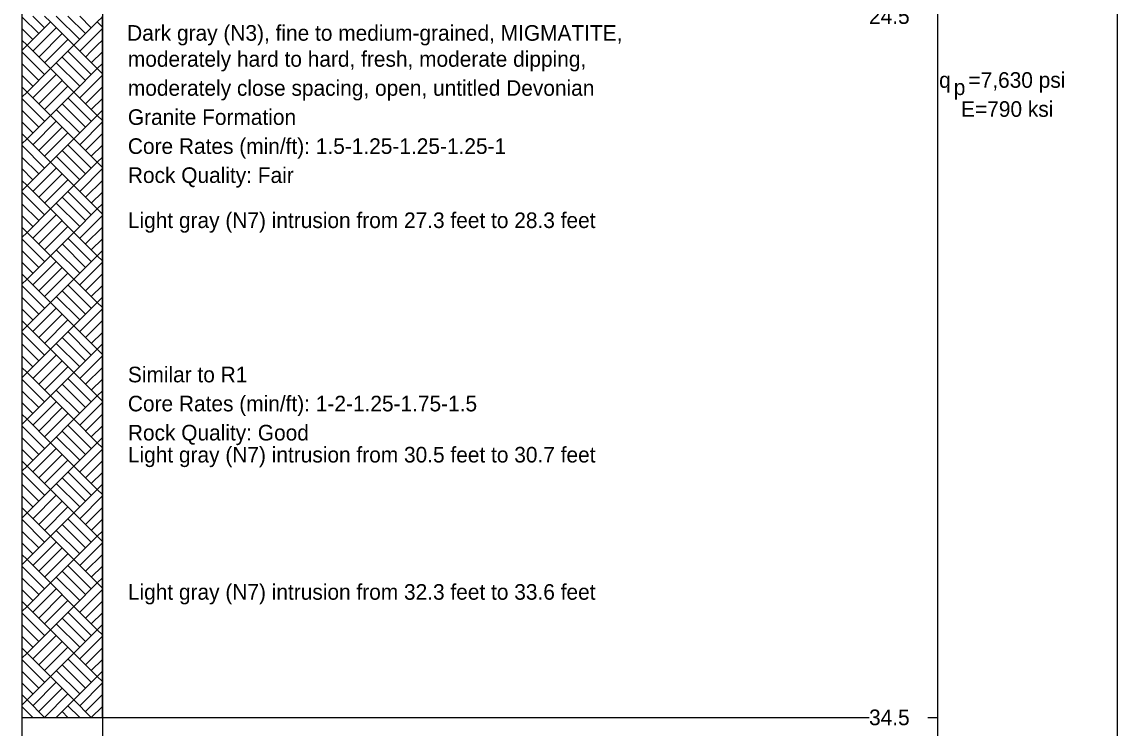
# Model space of a CAD drawing. Extents: x 9419 to 9552, y 6780 to 6865.
# Drawn here: x 9438.31 to 9453.95, y 6812.36 to 6822.43 of the extents above; entities that cross this region are included whole.
import ezdxf

# ---------------------------------------------------------------- set-up
doc = ezdxf.new("R2010")
doc.units = 0
doc.layers.add('7', color=7, linetype='Continuous')
doc.layers.add('8', color=7, linetype='Continuous')

msp = doc.modelspace()

# ---------------------------------------------------------------- linework, layer by layer
at = {"layer": '7'}
for p, q in [((9438.314, 6822.511), (9438.314, 6822.011)), ((9439.463, 6822.011), (9439.463, 6822.511)), ((9438.314, 6822.011), (9438.314, 6812.511)), ((9439.463, 6812.511), (9439.463, 6822.011)), ((9438.314, 6812.511), (9439.463, 6812.511))]:
    msp.add_line(p, q, dxfattribs=at)
for points in [[(9453.945, 6860.114), (9453.945, 6821.983)], [(9438.314, 6850.528), (9438.314, 6821.983)], [(9439.463, 6850.528), (9439.463, 6821.983)], [(9451.38, 6850.528), (9451.38, 6821.983)], [(9438.314, 6822.038), (9438.314, 6796.983)], [(9439.463, 6822.038), (9439.463, 6796.983)], [(9451.38, 6822.038), (9451.38, 6796.983)], [(9453.945, 6822.038), (9453.945, 6791.992)], [(9439.463, 6812.511), (9450.405, 6812.511)], [(9451.244, 6812.511), (9451.38, 6812.511)]]:
    msp.add_lwpolyline(points, dxfattribs=at)
at = {"layer": '8'}
for p, q in [((9438.314, 6822.501), (9438.555, 6822.261)), ((9438.722, 6822.427), (9438.389, 6822.094)), ((9438.722, 6822.427), (9438.389, 6822.094)), ((9438.472, 6822.511), (9438.639, 6822.344)), ((9438.639, 6822.511), (9438.722, 6822.427)), ((9439.055, 6822.094), (9438.722, 6822.427)), ((9438.722, 6822.427), (9439.055, 6822.094)), ((9438.805, 6822.511), (9439.139, 6822.177)), ((9438.972, 6822.511), (9439.222, 6822.261)), ((9439.389, 6822.427), (9439.055, 6822.094)), ((9439.139, 6822.511), (9439.305, 6822.344)), ((9439.463, 6822.501), (9439.389, 6822.427)), ((9439.389, 6822.427), (9439.463, 6822.353)), ((9438.314, 6822.335), (9438.472, 6822.177)), ((9438.805, 6822.344), (9438.472, 6822.011)), ((9438.889, 6822.261), (9438.555, 6821.927)), ((9439.463, 6822.335), (9439.139, 6822.011)), ((9438.314, 6822.168), (9438.389, 6822.094)), ((9438.389, 6822.094), (9438.314, 6822.02)), ((9438.389, 6822.094), (9438.722, 6821.761)), ((9438.972, 6822.177), (9438.639, 6821.844)), ((9439.055, 6822.094), (9438.722, 6821.761)), ((9439.055, 6822.094), (9439.389, 6821.761)), ((9439.389, 6822.094), (9439.305, 6822.011)), ((9439.389, 6822.094), (9439.305, 6822.011)), ((9439.463, 6822.168), (9439.389, 6822.094)), ((9439.463, 6822.168), (9439.389, 6822.094)), ((9438.314, 6822.001), (9438.639, 6821.677)), ((9438.472, 6822.011), (9438.472, 6822.011)), ((9438.889, 6821.927), (9439.222, 6821.594)), ((9438.972, 6822.011), (9439.305, 6821.677)), ((9439.139, 6822.011), (9439.139, 6822.011)), ((9439.305, 6822.011), (9439.222, 6821.927)), ((9439.463, 6822.001), (9439.305, 6821.844)), ((9438.314, 6821.835), (9438.555, 6821.594)), ((9438.722, 6821.761), (9438.389, 6821.427)), ((9438.722, 6821.761), (9438.389, 6821.427)), ((9439.055, 6821.427), (9438.722, 6821.761)), ((9438.722, 6821.761), (9439.055, 6821.427)), ((9438.805, 6821.844), (9439.139, 6821.511)), ((9439.389, 6821.761), (9439.055, 6821.427)), ((9439.389, 6821.761), (9439.055, 6821.427)), ((9439.463, 6821.835), (9439.389, 6821.761)), ((9439.463, 6821.835), (9439.389, 6821.761)), ((9439.463, 6821.687), (9439.389, 6821.761)), ((9439.389, 6821.761), (9439.463, 6821.687)), ((9438.314, 6821.668), (9438.472, 6821.511)), ((9438.805, 6821.677), (9438.472, 6821.344)), ((9438.889, 6821.594), (9438.555, 6821.261)), ((9439.463, 6821.668), (9439.139, 6821.344)), ((9438.389, 6821.427), (9438.314, 6821.501)), ((9438.389, 6821.427), (9438.314, 6821.353)), ((9438.389, 6821.427), (9438.722, 6821.094)), ((9438.972, 6821.511), (9438.639, 6821.177)), ((9439.055, 6821.427), (9438.722, 6821.094)), ((9439.055, 6821.427), (9438.722, 6821.094)), ((9439.055, 6821.427), (9439.389, 6821.094)), ((9439.463, 6821.501), (9439.222, 6821.261)), ((9438.314, 6821.335), (9438.639, 6821.011)), ((9438.972, 6821.344), (9439.305, 6821.011)), ((9439.463, 6821.335), (9439.305, 6821.177)), ((9438.314, 6821.168), (9438.555, 6820.927)), ((9438.805, 6821.177), (9439.139, 6820.844)), ((9438.889, 6821.261), (9439.222, 6820.927)), ((9439.463, 6821.168), (9439.389, 6821.094)), ((9439.463, 6821.168), (9439.389, 6821.094)), ((9438.314, 6821.001), (9438.472, 6820.844)), ((9438.722, 6821.094), (9438.389, 6820.761)), ((9438.722, 6821.094), (9438.389, 6820.761)), ((9438.805, 6821.011), (9438.472, 6820.677)), ((9439.055, 6820.761), (9438.722, 6821.094)), ((9438.722, 6821.094), (9439.055, 6820.761)), ((9439.389, 6821.094), (9439.055, 6820.761)), ((9439.389, 6821.094), (9439.055, 6820.761)), ((9439.463, 6821.001), (9439.139, 6820.677)), ((9439.463, 6821.02), (9439.389, 6821.094)), ((9439.389, 6821.094), (9439.463, 6821.02)), ((9438.389, 6820.761), (9438.314, 6820.835)), ((9438.889, 6820.927), (9438.555, 6820.594)), ((9438.972, 6820.844), (9438.639, 6820.511)), ((9439.463, 6820.835), (9439.222, 6820.594)), ((9438.389, 6820.761), (9438.314, 6820.687)), ((9438.314, 6820.668), (9438.639, 6820.344)), ((9438.389, 6820.761), (9438.722, 6820.427)), ((9439.055, 6820.761), (9438.722, 6820.427)), ((9439.055, 6820.761), (9438.722, 6820.427)), ((9438.972, 6820.677), (9439.305, 6820.344)), ((9439.055, 6820.761), (9439.389, 6820.427)), ((9439.463, 6820.668), (9439.305, 6820.511)), ((9438.314, 6820.501), (9438.555, 6820.261)), ((9438.805, 6820.511), (9439.139, 6820.177)), ((9438.889, 6820.594), (9439.222, 6820.261)), ((9439.463, 6820.501), (9439.389, 6820.427)), ((9439.463, 6820.501), (9439.389, 6820.427)), ((9438.314, 6820.335), (9438.472, 6820.177)), ((9438.722, 6820.427), (9438.389, 6820.094)), ((9438.722, 6820.427), (9438.389, 6820.094)), ((9438.805, 6820.344), (9438.472, 6820.011)), ((9439.055, 6820.094), (9438.722, 6820.427)), ((9438.722, 6820.427), (9439.055, 6820.094)), ((9439.389, 6820.427), (9439.055, 6820.094)), ((9439.389, 6820.427), (9439.055, 6820.094)), ((9439.463, 6820.335), (9439.139, 6820.011)), ((9439.463, 6820.353), (9439.389, 6820.427)), ((9439.389, 6820.427), (9439.463, 6820.353)), ((9438.889, 6820.261), (9438.555, 6819.927)), ((9438.972, 6820.177), (9438.639, 6819.844)), ((9438.389, 6820.094), (9438.314, 6820.168)), ((9438.389, 6820.094), (9438.314, 6820.02)), ((9438.389, 6820.094), (9438.722, 6819.761)), ((9439.055, 6820.094), (9438.722, 6819.761)), ((9439.055, 6820.094), (9438.722, 6819.761)), ((9439.055, 6820.094), (9439.389, 6819.761)), ((9439.463, 6820.168), (9439.222, 6819.927)), ((9438.314, 6820.001), (9438.639, 6819.677)), ((9438.889, 6819.927), (9439.222, 6819.594)), ((9438.972, 6820.011), (9439.305, 6819.677)), ((9439.463, 6820.001), (9439.305, 6819.844)), ((9438.314, 6819.835), (9438.555, 6819.594)), ((9438.722, 6819.761), (9438.389, 6819.427)), ((9438.722, 6819.761), (9438.389, 6819.427)), ((9439.055, 6819.427), (9438.722, 6819.761)), ((9438.722, 6819.761), (9439.055, 6819.427)), ((9438.805, 6819.844), (9439.139, 6819.511)), ((9439.389, 6819.761), (9439.055, 6819.427)), ((9439.389, 6819.761), (9439.055, 6819.427)), ((9439.463, 6819.835), (9439.389, 6819.761)), ((9439.463, 6819.835), (9439.389, 6819.761)), ((9439.463, 6819.687), (9439.389, 6819.761)), ((9439.389, 6819.761), (9439.463, 6819.687)), ((9438.314, 6819.668), (9438.472, 6819.511)), ((9438.805, 6819.677), (9438.472, 6819.344)), ((9438.889, 6819.594), (9438.555, 6819.261)), ((9439.463, 6819.668), (9439.139, 6819.344)), ((9438.389, 6819.427), (9438.314, 6819.501)), ((9438.389, 6819.427), (9438.314, 6819.353)), ((9438.389, 6819.427), (9438.722, 6819.094)), ((9438.972, 6819.511), (9438.639, 6819.177)), ((9439.055, 6819.427), (9438.722, 6819.094)), ((9439.055, 6819.427), (9438.722, 6819.094)), ((9439.055, 6819.427), (9439.389, 6819.094)), ((9439.463, 6819.501), (9439.222, 6819.261)), ((9438.314, 6819.335), (9438.639, 6819.011)), ((9438.889, 6819.261), (9439.222, 6818.927)), ((9438.972, 6819.344), (9439.305, 6819.011)), ((9439.463, 6819.335), (9439.305, 6819.177)), ((9438.314, 6819.168), (9438.555, 6818.927)), ((9438.722, 6819.094), (9438.389, 6818.761)), ((9438.722, 6819.094), (9438.389, 6818.761)), ((9439.055, 6818.761), (9438.722, 6819.094)), ((9438.722, 6819.094), (9439.055, 6818.761)), ((9438.805, 6819.177), (9439.139, 6818.844)), ((9439.389, 6819.094), (9439.055, 6818.761)), ((9439.389, 6819.094), (9439.055, 6818.761)), ((9439.463, 6819.168), (9439.389, 6819.094)), ((9439.463, 6819.168), (9439.389, 6819.094)), ((9439.463, 6819.02), (9439.389, 6819.094)), ((9439.389, 6819.094), (9439.463, 6819.02)), ((9438.314, 6819.001), (9438.472, 6818.844)), ((9438.805, 6819.011), (9438.472, 6818.677)), ((9438.889, 6818.927), (9438.555, 6818.594)), ((9439.463, 6819.001), (9439.139, 6818.677)), ((9438.389, 6818.761), (9438.314, 6818.835)), ((9438.972, 6818.844), (9438.639, 6818.511)), ((9439.463, 6818.835), (9439.222, 6818.594)), ((9438.389, 6818.761), (9438.314, 6818.687)), ((9438.314, 6818.668), (9438.639, 6818.344)), ((9438.389, 6818.761), (9438.722, 6818.427)), ((9439.055, 6818.761), (9438.722, 6818.427)), ((9439.055, 6818.761), (9438.722, 6818.427)), ((9438.972, 6818.677), (9439.305, 6818.344)), ((9439.055, 6818.761), (9439.389, 6818.427)), ((9439.463, 6818.668), (9439.305, 6818.511)), ((9438.314, 6818.501), (9438.555, 6818.261)), ((9438.805, 6818.511), (9439.139, 6818.177)), ((9438.889, 6818.594), (9439.222, 6818.261)), ((9439.463, 6818.501), (9439.389, 6818.427)), ((9439.463, 6818.501), (9439.389, 6818.427)), ((9438.314, 6818.335), (9438.472, 6818.177)), ((9438.722, 6818.427), (9438.389, 6818.094)), ((9438.722, 6818.427), (9438.389, 6818.094)), ((9438.805, 6818.344), (9438.472, 6818.011)), ((9439.055, 6818.094), (9438.722, 6818.427)), ((9438.722, 6818.427), (9439.055, 6818.094)), ((9439.389, 6818.427), (9439.055, 6818.094)), ((9439.389, 6818.427), (9439.055, 6818.094)), ((9439.463, 6818.335), (9439.139, 6818.011)), ((9439.463, 6818.353), (9439.389, 6818.427)), ((9439.389, 6818.427), (9439.463, 6818.353)), ((9438.389, 6818.094), (9438.314, 6818.168)), ((9438.889, 6818.261), (9438.555, 6817.927)), ((9438.972, 6818.177), (9438.639, 6817.844)), ((9439.463, 6818.168), (9439.222, 6817.927)), ((9438.389, 6818.094), (9438.314, 6818.02)), ((9438.314, 6818.001), (9438.639, 6817.677)), ((9438.389, 6818.094), (9438.722, 6817.761)), ((9439.055, 6818.094), (9438.722, 6817.761)), ((9439.055, 6818.094), (9438.722, 6817.761)), ((9438.972, 6818.011), (9439.305, 6817.677)), ((9439.055, 6818.094), (9439.389, 6817.761)), ((9439.463, 6818.001), (9439.305, 6817.844)), ((9438.314, 6817.835), (9438.555, 6817.594)), ((9438.805, 6817.844), (9439.139, 6817.511)), ((9438.889, 6817.927), (9439.222, 6817.594)), ((9439.463, 6817.835), (9439.389, 6817.761)), ((9439.463, 6817.835), (9439.389, 6817.761)), ((9438.722, 6817.761), (9438.389, 6817.427)), ((9438.722, 6817.761), (9438.389, 6817.427)), ((9438.805, 6817.677), (9438.472, 6817.344)), ((9439.055, 6817.427), (9438.722, 6817.761)), ((9438.722, 6817.761), (9439.055, 6817.427)), ((9439.389, 6817.761), (9439.055, 6817.427)), ((9439.389, 6817.761), (9439.055, 6817.427)), ((9439.463, 6817.687), (9439.389, 6817.761)), ((9439.389, 6817.761), (9439.463, 6817.687)), ((9438.314, 6817.668), (9438.472, 6817.511)), ((9438.889, 6817.594), (9438.555, 6817.261)), ((9439.463, 6817.668), (9439.139, 6817.344)), ((9438.389, 6817.427), (9438.314, 6817.501)), ((9438.389, 6817.427), (9438.314, 6817.353)), ((9438.389, 6817.427), (9438.722, 6817.094)), ((9438.972, 6817.511), (9438.639, 6817.177)), ((9439.055, 6817.427), (9438.722, 6817.094)), ((9439.055, 6817.427), (9438.722, 6817.094)), ((9439.055, 6817.427), (9439.389, 6817.094)), ((9439.463, 6817.501), (9439.222, 6817.261)), ((9438.314, 6817.335), (9438.639, 6817.011)), ((9438.889, 6817.261), (9439.222, 6816.927)), ((9438.972, 6817.344), (9439.305, 6817.011)), ((9439.463, 6817.335), (9439.305, 6817.177)), ((9438.314, 6817.168), (9438.555, 6816.927)), ((9438.722, 6817.094), (9438.389, 6816.761)), ((9438.722, 6817.094), (9438.389, 6816.761)), ((9439.055, 6816.761), (9438.722, 6817.094)), ((9438.722, 6817.094), (9439.055, 6816.761)), ((9438.805, 6817.177), (9439.139, 6816.844)), ((9439.389, 6817.094), (9439.055, 6816.761)), ((9439.389, 6817.094), (9439.055, 6816.761)), ((9439.463, 6817.168), (9439.389, 6817.094)), ((9439.463, 6817.168), (9439.389, 6817.094)), ((9439.463, 6817.02), (9439.389, 6817.094)), ((9439.389, 6817.094), (9439.463, 6817.02)), ((9438.314, 6817.001), (9438.472, 6816.844)), ((9438.805, 6817.011), (9438.472, 6816.677)), ((9438.889, 6816.927), (9438.555, 6816.594)), ((9439.463, 6817.001), (9439.139, 6816.677)), ((9438.389, 6816.761), (9438.314, 6816.835)), ((9438.389, 6816.761), (9438.314, 6816.687)), ((9438.389, 6816.761), (9438.722, 6816.427)), ((9438.972, 6816.844), (9438.639, 6816.511)), ((9439.055, 6816.761), (9438.722, 6816.427)), ((9439.055, 6816.761), (9438.722, 6816.427)), ((9439.055, 6816.761), (9439.389, 6816.427)), ((9439.463, 6816.835), (9439.222, 6816.594)), ((9438.314, 6816.668), (9438.639, 6816.344)), ((9438.889, 6816.594), (9439.222, 6816.261)), ((9438.972, 6816.677), (9439.305, 6816.344)), ((9439.463, 6816.668), (9439.305, 6816.511)), ((9438.314, 6816.501), (9438.555, 6816.261)), ((9438.722, 6816.427), (9438.389, 6816.094)), ((9438.722, 6816.427), (9438.389, 6816.094)), ((9439.055, 6816.094), (9438.722, 6816.427)), ((9438.722, 6816.427), (9439.055, 6816.094)), ((9438.805, 6816.511), (9439.139, 6816.177)), ((9439.389, 6816.427), (9439.055, 6816.094)), ((9439.389, 6816.427), (9439.055, 6816.094)), ((9439.463, 6816.501), (9439.389, 6816.427)), ((9439.463, 6816.501), (9439.389, 6816.427)), ((9439.463, 6816.353), (9439.389, 6816.427)), ((9439.389, 6816.427), (9439.463, 6816.353)), ((9438.314, 6816.335), (9438.472, 6816.177)), ((9438.805, 6816.344), (9438.472, 6816.011)), ((9439.463, 6816.335), (9439.139, 6816.011)), ((9438.389, 6816.094), (9438.314, 6816.168)), ((9438.889, 6816.261), (9438.555, 6815.927)), ((9438.972, 6816.177), (9438.639, 6815.844)), ((9439.463, 6816.168), (9439.222, 6815.927)), ((9438.389, 6816.094), (9438.314, 6816.02)), ((9438.314, 6816.001), (9438.639, 6815.677)), ((9438.389, 6816.094), (9438.722, 6815.761)), ((9439.055, 6816.094), (9438.722, 6815.761)), ((9439.055, 6816.094), (9438.722, 6815.761)), ((9438.972, 6816.011), (9439.305, 6815.677)), ((9439.055, 6816.094), (9439.389, 6815.761)), ((9439.463, 6816.001), (9439.305, 6815.844)), ((9438.314, 6815.835), (9438.555, 6815.594)), ((9438.805, 6815.844), (9439.139, 6815.511)), ((9438.889, 6815.927), (9439.222, 6815.594)), ((9439.463, 6815.835), (9439.389, 6815.761)), ((9439.463, 6815.835), (9439.389, 6815.761)), ((9438.314, 6815.668), (9438.472, 6815.511)), ((9438.722, 6815.761), (9438.389, 6815.427)), ((9438.722, 6815.761), (9438.389, 6815.427)), ((9438.805, 6815.677), (9438.472, 6815.344)), ((9439.055, 6815.427), (9438.722, 6815.761)), ((9438.722, 6815.761), (9439.055, 6815.427)), ((9439.389, 6815.761), (9439.055, 6815.427)), ((9439.389, 6815.761), (9439.055, 6815.427)), ((9439.463, 6815.668), (9439.139, 6815.344)), ((9439.463, 6815.687), (9439.389, 6815.761)), ((9439.389, 6815.761), (9439.463, 6815.687)), ((9438.389, 6815.427), (9438.314, 6815.501)), ((9438.889, 6815.594), (9438.555, 6815.261)), ((9438.972, 6815.511), (9438.639, 6815.177)), ((9439.463, 6815.501), (9439.222, 6815.261)), ((9438.389, 6815.427), (9438.314, 6815.353)), ((9438.314, 6815.335), (9438.639, 6815.011)), ((9438.389, 6815.427), (9438.722, 6815.094)), ((9439.055, 6815.427), (9438.722, 6815.094)), ((9439.055, 6815.427), (9438.722, 6815.094)), ((9438.972, 6815.344), (9439.305, 6815.011)), ((9439.055, 6815.427), (9439.389, 6815.094)), ((9439.463, 6815.335), (9439.305, 6815.177)), ((9438.805, 6815.177), (9439.139, 6814.844)), ((9438.889, 6815.261), (9439.222, 6814.927)), ((9438.314, 6815.168), (9438.555, 6814.927)), ((9438.722, 6815.094), (9438.389, 6814.761)), ((9438.722, 6815.094), (9438.389, 6814.761)), ((9439.055, 6814.761), (9438.722, 6815.094)), ((9438.722, 6815.094), (9439.055, 6814.761)), ((9439.389, 6815.094), (9439.055, 6814.761)), ((9439.389, 6815.094), (9439.055, 6814.761)), ((9439.463, 6815.168), (9439.389, 6815.094)), ((9439.463, 6815.168), (9439.389, 6815.094)), ((9439.463, 6815.02), (9439.389, 6815.094)), ((9439.389, 6815.094), (9439.463, 6815.02)), ((9438.314, 6815.001), (9438.472, 6814.844)), ((9438.805, 6815.011), (9438.472, 6814.677)), ((9438.889, 6814.927), (9438.555, 6814.594)), ((9439.463, 6815.001), (9439.139, 6814.677)), ((9438.389, 6814.761), (9438.314, 6814.835)), ((9438.389, 6814.761), (9438.314, 6814.687)), ((9438.389, 6814.761), (9438.722, 6814.427)), ((9438.972, 6814.844), (9438.639, 6814.511)), ((9439.055, 6814.761), (9438.722, 6814.427)), ((9439.055, 6814.761), (9438.722, 6814.427)), ((9439.055, 6814.761), (9439.389, 6814.427)), ((9439.463, 6814.835), (9439.222, 6814.594)), ((9438.314, 6814.668), (9438.639, 6814.344)), ((9438.889, 6814.594), (9439.222, 6814.261)), ((9438.972, 6814.677), (9439.305, 6814.344)), ((9439.463, 6814.668), (9439.305, 6814.511)), ((9438.314, 6814.501), (9438.555, 6814.261)), ((9438.722, 6814.427), (9438.389, 6814.094)), ((9438.722, 6814.427), (9438.389, 6814.094)), ((9439.055, 6814.094), (9438.722, 6814.427)), ((9438.722, 6814.427), (9439.055, 6814.094)), ((9438.805, 6814.511), (9439.139, 6814.177)), ((9439.389, 6814.427), (9439.055, 6814.094)), ((9439.389, 6814.427), (9439.055, 6814.094)), ((9439.463, 6814.501), (9439.389, 6814.427)), ((9439.463, 6814.501), (9439.389, 6814.427)), ((9439.463, 6814.353), (9439.389, 6814.427)), ((9439.389, 6814.427), (9439.463, 6814.353)), ((9438.314, 6814.335), (9438.472, 6814.177)), ((9438.805, 6814.344), (9438.472, 6814.011)), ((9438.889, 6814.261), (9438.555, 6813.927)), ((9439.463, 6814.335), (9439.139, 6814.011)), ((9438.389, 6814.094), (9438.314, 6814.168)), ((9438.389, 6814.094), (9438.314, 6814.02)), ((9438.389, 6814.094), (9438.722, 6813.761)), ((9438.972, 6814.177), (9438.639, 6813.844)), ((9439.055, 6814.094), (9438.722, 6813.761)), ((9439.055, 6814.094), (9438.722, 6813.761)), ((9439.055, 6814.094), (9439.389, 6813.761)), ((9439.463, 6814.168), (9439.222, 6813.927)), ((9438.314, 6814.001), (9438.639, 6813.677)), ((9438.889, 6813.927), (9439.222, 6813.594)), ((9438.972, 6814.011), (9439.305, 6813.677)), ((9439.463, 6814.001), (9439.305, 6813.844)), ((9438.314, 6813.835), (9438.555, 6813.594)), ((9438.805, 6813.844), (9439.139, 6813.511)), ((9439.463, 6813.835), (9439.389, 6813.761)), ((9439.463, 6813.835), (9439.389, 6813.761)), ((9438.314, 6813.668), (9438.472, 6813.511)), ((9438.722, 6813.761), (9438.389, 6813.427)), ((9438.722, 6813.761), (9438.389, 6813.427)), ((9438.805, 6813.677), (9438.472, 6813.344)), ((9439.055, 6813.427), (9438.722, 6813.761)), ((9438.722, 6813.761), (9439.055, 6813.427)), ((9439.389, 6813.761), (9439.055, 6813.427)), ((9439.389, 6813.761), (9439.055, 6813.427)), ((9439.463, 6813.668), (9439.139, 6813.344)), ((9439.463, 6813.687), (9439.389, 6813.761)), ((9439.389, 6813.761), (9439.463, 6813.687)), ((9438.389, 6813.427), (9438.314, 6813.501)), ((9438.889, 6813.594), (9438.555, 6813.261)), ((9438.972, 6813.511), (9438.639, 6813.177)), ((9439.463, 6813.501), (9439.222, 6813.261)), ((9438.389, 6813.427), (9438.314, 6813.353)), ((9438.314, 6813.335), (9438.639, 6813.011)), ((9438.389, 6813.427), (9438.722, 6813.094)), ((9439.055, 6813.427), (9438.722, 6813.094)), ((9439.055, 6813.427), (9438.722, 6813.094)), ((9438.972, 6813.344), (9439.305, 6813.011)), ((9439.055, 6813.427), (9439.389, 6813.094)), ((9439.463, 6813.335), (9439.305, 6813.177)), ((9438.314, 6813.168), (9438.555, 6812.927)), ((9438.805, 6813.177), (9439.139, 6812.844)), ((9438.889, 6813.261), (9439.222, 6812.927)), ((9439.463, 6813.168), (9439.389, 6813.094)), ((9439.463, 6813.168), (9439.389, 6813.094)), ((9438.314, 6813.001), (9438.472, 6812.844)), ((9438.722, 6813.094), (9438.389, 6812.761)), ((9438.722, 6813.094), (9438.389, 6812.761)), ((9438.805, 6813.011), (9438.472, 6812.677)), ((9439.055, 6812.761), (9438.722, 6813.094)), ((9438.722, 6813.094), (9439.055, 6812.761)), ((9439.389, 6813.094), (9439.055, 6812.761)), ((9439.389, 6813.094), (9439.055, 6812.761)), ((9439.463, 6813.001), (9439.139, 6812.677)), ((9439.463, 6813.02), (9439.389, 6813.094)), ((9439.389, 6813.094), (9439.463, 6813.02)), ((9438.389, 6812.761), (9438.314, 6812.835)), ((9438.889, 6812.927), (9438.555, 6812.594)), ((9438.972, 6812.844), (9438.639, 6812.511)), ((9439.463, 6812.835), (9439.222, 6812.594)), ((9438.389, 6812.761), (9438.314, 6812.687)), ((9438.389, 6812.761), (9438.639, 6812.511)), ((9439.055, 6812.761), (9438.805, 6812.511)), ((9439.055, 6812.761), (9438.805, 6812.511)), ((9438.972, 6812.677), (9439.139, 6812.511)), ((9439.055, 6812.761), (9439.305, 6812.511)), ((9438.314, 6812.668), (9438.472, 6812.511)), ((9438.889, 6812.594), (9438.972, 6812.511)), ((9439.463, 6812.668), (9439.305, 6812.511)), ((9438.805, 6812.511), (9438.805, 6812.511))]:
    msp.add_line(p, q, dxfattribs=at)

# ---------------------------------------------------------------- texts
at = {"layer": '7'}
for s, height, p in [('24.5', 0.2228, (9450.405, 6822.399)), ('Dark gray (N3), fine to medium-grained, MIGMATITE,', 0.2228, (9439.816, 6822.159)), ('moderately hard to hard, fresh, moderate dipping,', 0.2228, (9439.827, 6821.788)), ('moderately close spacing, open, untitled Devonian', 0.2228, (9439.827, 6821.374)), ('q', 0.223, (9451.405, 6821.488)), ('=7,630 psi', 0.2228, (9451.824, 6821.488)), ('p', 0.223, (9451.614, 6821.384)), ('E=790 ksi', 0.2228, (9451.719, 6821.074)), ('Granite Formation', 0.2228, (9439.827, 6820.959)), ('Core Rates (min/ft): 1.5-1.25-1.25-1.25-1', 0.2228, (9439.827, 6820.545)), ('Rock Quality: Fair', 0.2228, (9439.827, 6820.131)), ('Light gray (N7) intrusion from 27.3 feet to 28.3 feet', 0.2228, (9439.827, 6819.488)), ('Similar to R1', 0.2228, (9439.827, 6817.288)), ('Core Rates (min/ft): 1-2-1.25-1.75-1.5', 0.2228, (9439.827, 6816.874)), ('Rock Quality: Good', 0.2228, (9439.827, 6816.459)), ('Light gray (N7) intrusion from 30.5 feet to 30.7 feet', 0.2228, (9439.827, 6816.145)), ('Light gray (N7) intrusion from 32.3 feet to 33.6 feet', 0.2228, (9439.827, 6814.188)), ('34.5', 0.2228, (9450.405, 6812.399))]:
    msp.add_text(s, height=height, dxfattribs=at).set_placement(p)

doc.saveas('drawing.dxf')
